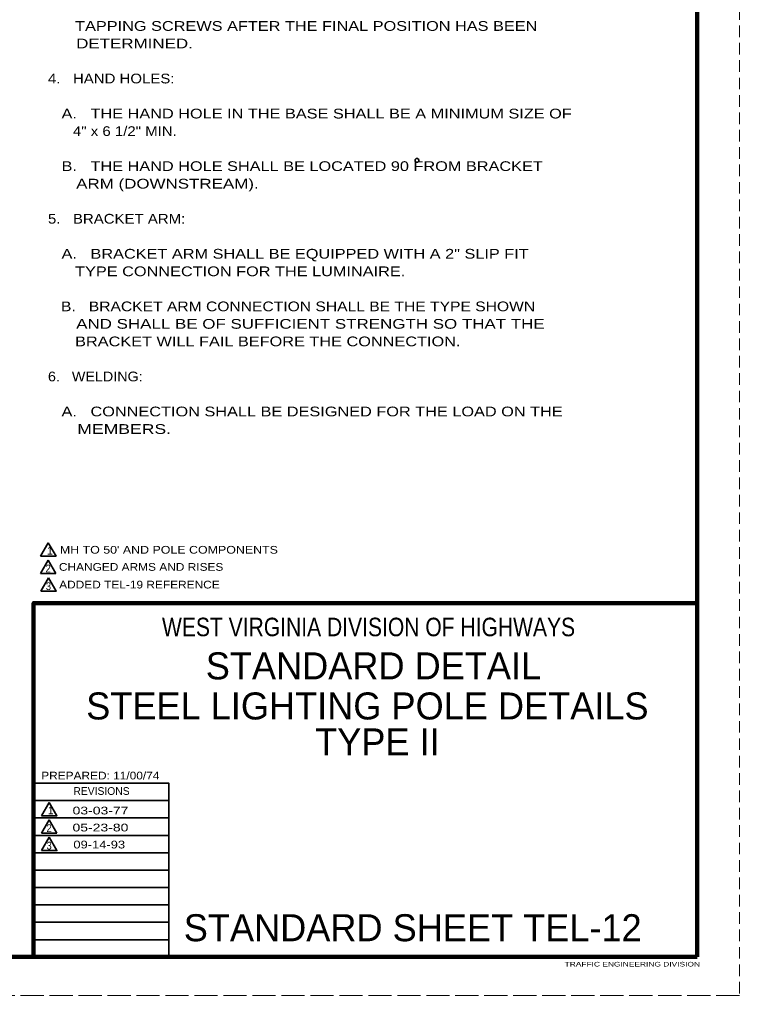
# Model space of a CAD drawing. Extents: x 6488 to 7168, y 276 to 716.
# Drawn here: x 6981.4 to 7167.7, y 276 to 528.6 of the extents above; entities that cross this region are included whole.
import ezdxf
from ezdxf.enums import TextEntityAlignment as Align

# ---------------------------------------------------------------- set-up
doc = ezdxf.new("R2010")
doc.units = 0
doc.linetypes.add('LONG_DASHED', pattern=[7.5, 6, -1.5])
doc.linetypes.add('MEDIUM_DASHED', pattern=[4.5, 3, -1.5])
doc.layers.add('1', color=7, linetype='Continuous', lineweight=35)
doc.layers.add('61', color=7, linetype='Continuous', lineweight=35)

msp = doc.modelspace()

# ---------------------------------------------------------------- linework, layer by layer
at = {"layer": '1', "linetype": 'MEDIUM_DASHED', "lineweight": 13}
msp.add_line((7167.663, 716.04), (7167.643, 276.02), dxfattribs=at)
at = {"layer": '1'}
for p, q in [((6988.833, 393.174), (6986.833, 389.71)), ((6988.8, 388.703), (6986.8, 385.239)), ((6988.8, 388.703), (6990.8, 385.239)), ((6990.8, 385.239), (6986.8, 385.239)), ((6988.868, 384.128), (6986.868, 380.664)), ((7020.043, 326.44), (6985.063, 326.44)), ((6989.063, 325.969), (6987.063, 322.505)), ((7020.043, 321.94), (6985.063, 321.94)), ((6989.03, 321.497), (6987.03, 318.033)), ((6989.03, 321.497), (6991.03, 318.033)), ((7020.043, 317.44), (6985.063, 317.44)), ((6991.03, 318.033), (6987.03, 318.033)), ((6989.056, 316.97), (6987.056, 313.506)), ((7020.043, 312.92), (6985.063, 312.92)), ((7020.043, 308.44), (6985.063, 308.44)), ((7020.043, 303.96), (6985.063, 303.96)), ((7020.043, 299.46), (6985.063, 299.46)), ((7020.043, 294.96), (6985.063, 294.96)), ((7020.043, 290.44), (6985.063, 290.44))]:
    msp.add_line(p, q, dxfattribs=at)
for points in [[(6988.833, 393.174), (6990.833, 389.71), (6986.833, 389.71)], [(6988.868, 384.128), (6990.868, 380.664), (6986.868, 380.664)], [(7020.043, 285.96), (7020.043, 330.92), (6985.063, 330.92)], [(6989.063, 325.969), (6991.063, 322.505), (6987.063, 322.505)], [(6989.056, 316.97), (6991.056, 313.506), (6987.056, 313.506)]]:
    msp.add_lwpolyline(points, dxfattribs=at)
at = {"layer": '1', "lineweight": 158}
msp.add_lwpolyline([(6985.043, 286), (6985.043, 377.58), (7156.703, 377.58)], dxfattribs=at)
at = {"layer": '1'}
msp.add_circle((7084.216, 492.148), 0.481, dxfattribs=at)
at = {"layer": '61', "lineweight": 158}
for p, q in [((7156.683, 706.04), (7156.703, 286)), ((7156.703, 286), (6517.643, 286.02))]:
    msp.add_line(p, q, dxfattribs=at)
at = {"layer": '61', "linetype": 'LONG_DASHED', "lineweight": 13}
msp.add_line((7167.643, 276.02), (6487.583, 276), dxfattribs=at)

# ---------------------------------------------------------------- texts
at = {"layer": '1'}
for s, height, width, p in [('      TAPPING SCREWS AFTER THE FINAL POSITION HAS BEEN', 2.52, 1.25, (6988.744, 525.672)), ('      DETERMINED.', 2.52, 1.3, (6988.744, 521.132)), ('4.   HAND HOLES:', 2.52, 1.15, (6988.744, 512.072)), ('   A.   THE HAND HOLE IN THE BASE SHALL BE A MINIMUM SIZE OF', 2.52, 1.25, (6988.744, 502.992)), ('      4" x 6 1/2" MIN.', 2.52, 1.15, (6988.744, 498.452)), ('   B.   THE HAND HOLE SHALL BE LOCATED 90 FROM BRACKET', 2.52, 1.25, (6988.744, 489.392)), ('      ARM (DOWNSTREAM).', 2.52, 1.3, (6988.744, 484.852)), ('5.   BRACKET ARM:', 2.52, 1.15, (6988.744, 475.772)), ('   A.   BRACKET ARM SHALL BE EQUIPPED WITH A 2" SLIP FIT', 2.52, 1.25, (6988.744, 466.712)), ('      TYPE CONNECTION FOR THE LUMINAIRE.', 2.52, 1.25, (6988.744, 462.172)), ('   B.   BRACKET ARM CONNECTION SHALL BE THE TYPE SHOWN', 2.52, 1.2, (6988.744, 453.092)), ('      AND SHALL BE OF SUFFICIENT STRENGTH SO THAT THE', 2.52, 1.3, (6988.744, 448.572)), ('      BRACKET WILL FAIL BEFORE THE CONNECTION.', 2.52, 1.25, (6988.744, 444.032)), ('6.   WELDING:', 2.52, 1.1, (6988.744, 434.952)), ('   A.   CONNECTION SHALL BE DESIGNED FOR THE LOAD ON THE', 2.52, 1.25, (6988.744, 425.892)), ('      MEMBERS. ', 2.52, 1.35, (6988.744, 421.352)), ("MH TO 50' AND POLE COMPONENTS", 2, 1.2, (6991.819, 390.355)), ('2', 2, 0.9, (6988.131, 385.507)), ('CHANGED ARMS AND RISES', 2, 1.15, (6991.575, 385.92)), ('3', 2, 0.9, (6988.2, 380.932)), ('ADDED TEL-19 REFERENCE', 2, 1.15, (6991.644, 381.345)), ('PREPARED: 11/00/74', 1.998, 1.15, (6987.003, 331.92)), ('2', 2, 0.9, (6988.362, 318.301)), ('3', 2, 0.9, (6988.387, 313.774)), ('TRAFFIC ENGINEERING DIVISION', 1.2, 1.35, (7122.423, 283.5))]:
    msp.add_text(s, height=height, dxfattribs=dict(at, width=width)).set_placement(p)
for s, height, p in [('1', 2, (6988.493, 390.11)), ('REVISIONS', 1.998, (6995.323, 327.92)), ('1', 2, (6988.723, 322.904)), ('STANDARD SHEET TEL-12', 6.993, (7023.883, 290.04))]:
    msp.add_text(s, height=height, dxfattribs=at).set_placement(p)
for s, height, width, p in [('WEST VIRGINIA DIVISION OF HIGHWAYS', 4.795, 0.85, (7071.691, 368.98)), ('03-03-77', 2, 1.35, (7002.343, 322.86)), ('05-23-80', 2, 1.35, (7002.323, 318.46)), ('09-14-93', 2, 1.25, (7002.012, 314.06))]:
    msp.add_text(s, height=height, dxfattribs=dict(at, width=width)).set_placement(p, align=Align.CENTER)
for s, p in [('STANDARD DETAIL', (7072.96, 357.82)), ('STEEL LIGHTING POLE DETAILS', (7071.387, 347.439)), ('TYPE II', (7073.982, 338.127))]:
    msp.add_text(s, height=6.993, dxfattribs=at).set_placement(p, align=Align.CENTER)

doc.saveas('drawing.dxf')
